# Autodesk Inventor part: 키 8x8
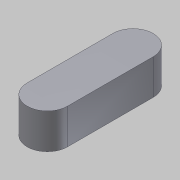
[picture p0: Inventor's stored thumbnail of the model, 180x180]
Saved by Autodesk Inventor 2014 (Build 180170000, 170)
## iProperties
Company: 한국ATC센터
Created: 2014-10
Part Number: 키 8x8
Document SubType Name: Modeling
Designer: 한국ATC센터
Density: 7.86 g/cm^3
Material: 강, 연강
Mass: 10.2483 g
Surface Area: 7.8646 cm^2
Volume: 1.30386 cm^3
Appearance: 강철
Author: KYOUNG IL JANG
Revision Number: 1
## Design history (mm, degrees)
sketch "스케치1"
  geometry: L1 (28.264, -14)-(28.264, -31) reference; L2 (20.264, -31)-(20.264, -14) reference; A1 r 4 centre (24.264, -31) between (20.264, -31) and (28.264, -31) reference; A2 r 4 centre (24.264, -14) between (28.264, -14) and (20.264, -14) reference; 1 further point
extrude "돌출1" new body sketch "스케치1" distance "d0" = 7; taper "d1" = 0 deg
node "솔리드1"
node "참조1"
